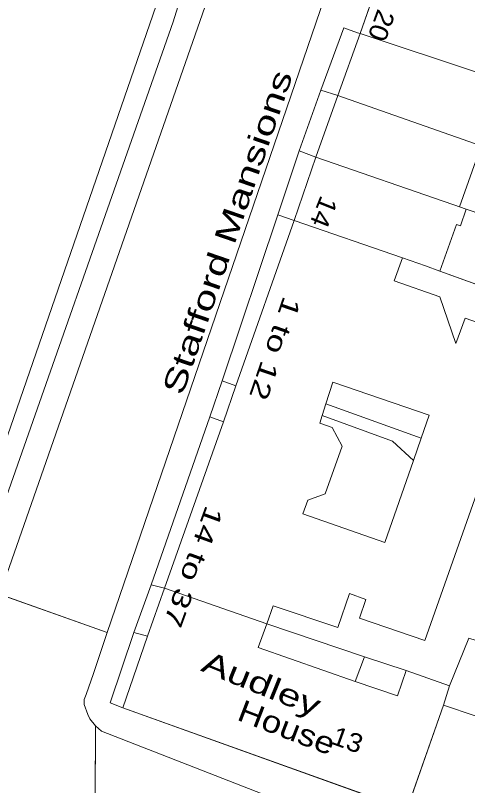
# Model space of a CAD drawing. Extents: x 528790 to 529292, y 179350 to 179856.
# Drawn here: x 529073.1 to 529109.4, y 179400.8 to 179462.8 of the extents above; entities that cross this region are included whole.
import ezdxf

# ---------------------------------------------------------------- set-up
doc = ezdxf.new("R2010")
doc.units = 0
doc.header["$LTSCALE"] = 0.6
doc.layers.add('1', color=7, linetype='Continuous', lineweight=13)
doc.layers.add('2', color=7, linetype='Continuous', lineweight=13)
doc.layers.add('5', color=7, linetype='Continuous')

msp = doc.modelspace()

# ---------------------------------------------------------------- linework, layer by layer
at = {"layer": '1'}
for points in [[(529114.4, 179506.25), (529113.95, 179506.4), (529113.55, 179506.6), (529113.05, 179506.9), (529109.35, 179500.6), (529109, 179500), (529106.6, 179495.95), (529103.106, 179489.891), (529101.15, 179486.5), (529097.9, 179480.65), (529096.6, 179478.45), (529092.35, 179471.1), (529087.2, 179468), (529087.15, 179466.8), (529086.55, 179464.8), (529085.75, 179462.3), (529070.05, 179417.6)], [(529068.6, 179417.95), (529086.15, 179468.75), (529075.3, 179473.5), (529070.95, 179475.45)], [(529104.55, 179398.9), (529081.7, 179407.1), (529080.7, 179407.5), (529082.6, 179413.15), (529084, 179417), (529088.7, 179430.5), (529089.7, 179433.4), (529094.18, 179446.76), (529095.9, 179451.9), (529097.65, 179456.8), (529099.5, 179461.8), (529100.6, 179461.4), (529100.8, 179461.35), (529102.6, 179466.5)], [(529098.25, 179465.2), (529080.46, 179413.16), (529079.34, 179409.86), (529078.75, 179408.15), (529078.6, 179407.75), (529078.6, 179407.35), (529078.9, 179406.55), (529079.05, 179406.2), (529079.5, 179405.65), (529080, 179405.2), (529096.7, 179398.7)], [(529072.2, 179417.3), (529088.7, 179464.65)], [(529118.65, 179438.1), (529107.225, 179442.232), (529106.05, 179442.65), (529104.2, 179443.3), (529103.55, 179441.45), (529107.2, 179440.15), (529108.5, 179436.4), (529109.25, 179438.45), (529114.5, 179436.6), (529106, 179412.5), (529100.75, 179414.3), (529101.25, 179415.8), (529099.95, 179416.3), (529099, 179413.55), (529093.8, 179415.3), (529093.3, 179413.85), (529101.15, 179411.2), (529104.5, 179410.1), (529108, 179408.85), (529109.55, 179412.7)], [(529079.47, 179394.39), (529079.5, 179405.65), (529079.05, 179406.2), (529078.9, 179406.55), (529078.6, 179407.35), (529078.6, 179407.75), (529078.75, 179408.15), (529079.34, 179409.86), (529080.46, 179413.16), (529071.39, 179416.36)], [(529096.7, 179398.7), (529080, 179405.2), (529079.5, 179405.65), (529079.47, 179394.39)]]:
    msp.add_lwpolyline(points, dxfattribs=at)
for points in [[(529098.25, 179465.2), (529099.6, 179467.2), (529101.25, 179469.3), (529102.95, 179471.55), (529104.35, 179473.5), (529107.6, 179479.8), (529101.31, 179483.07), (529100.25, 179481.25), (529098.95, 179478.8), (529097.6, 179476.3), (529096.35, 179473.9), (529094.8, 179471.55), (529094, 179470.3), (529093, 179469.05), (529089.8, 179465.7), (529088.7, 179464.65), (529072.2, 179417.3), (529072, 179416.9), (529071.7, 179416.55), (529071.39, 179416.36), (529080.46, 179413.16)], [(529085.75, 179462.3), (529086.55, 179464.8), (529087.15, 179466.8), (529087.2, 179468), (529086.5, 179469.6), (529076.4, 179475.4), (529075.3, 179473.5), (529086.15, 179468.75), (529068.6, 179417.95), (529070.05, 179417.6)], [(529114.2, 179462.65), (529110.6, 179464.05), (529110.25, 179464.2), (529102.6, 179466.5), (529100.8, 179461.35), (529110.4, 179458.15), (529111.6, 179461.5), (529113.55, 179460.8)], [(529100.8, 179461.35), (529100.6, 179461.4), (529099.5, 179461.8), (529097.65, 179456.8), (529099, 179456.35)], [(529110.55, 179452.3), (529117.6, 179449.9), (529118.95, 179450.5), (529119.8, 179453.05), (529119.15, 179454.65), (529110.4, 179458.15), (529100.8, 179461.35), (529099, 179456.35)], [(529097.25, 179451.4), (529099, 179456.35), (529097.65, 179456.8), (529095.9, 179451.9)], [(529108.802, 179447.406), (529110.55, 179452.3), (529099, 179456.35), (529097.25, 179451.4), (529108.25, 179447.599), (529108.426, 179447.536)], [(529095.9, 179451.9), (529094.18, 179446.76), (529095.5, 179446.3), (529097.25, 179451.4)], [(529121.65, 179446.25), (529122.4, 179448.3), (529117.6, 179449.9), (529110.55, 179452.3), (529108.802, 179447.406), (529109.342, 179447.216), (529120.62, 179443.39)], [(529109.342, 179447.216), (529108.802, 179447.406), (529108.426, 179447.536), (529108.25, 179447.599), (529097.25, 179451.4), (529095.5, 179446.3), (529104.2, 179443.3), (529106.05, 179442.65), (529107.225, 179442.232), (529108.544, 179445.988), (529108.87, 179445.874)], [(529090.8, 179433), (529095.5, 179446.3), (529094.18, 179446.76), (529089.7, 179433.4)], [(529109.342, 179447.216), (529108.87, 179445.874), (529108.544, 179445.988), (529107.225, 179442.232), (529118.65, 179438.1), (529120.62, 179443.39)], [(529095.5, 179446.3), (529090.8, 179433), (529089.8, 179430.1), (529085.05, 179416.71), (529093.3, 179413.85), (529093.8, 179415.3), (529099, 179413.55), (529099.95, 179416.3), (529101.25, 179415.8), (529100.75, 179414.3), (529106, 179412.5), (529114.5, 179436.6), (529109.25, 179438.45), (529108.5, 179436.4), (529107.2, 179440.15), (529103.55, 179441.45), (529104.2, 179443.3)], [(529089.8, 179430.1), (529090.8, 179433), (529089.7, 179433.4), (529088.7, 179430.5)], [(529105.1, 179427), (529102.8, 179420.4), (529096.2, 179422.7), (529096.6, 179423.8), (529098, 179424.3), (529099.35, 179428.15), (529098.55, 179429.65), (529097.55, 179430), (529097.75, 179430.6), (529098.05, 179431.55), (529098.6, 179433.3), (529106.35, 179430.65), (529105.7, 179428.8)], [(529105.7, 179428.8), (529106.35, 179430.65), (529098.6, 179433.3), (529098.05, 179431.55)], [(529098.05, 179431.55), (529097.75, 179430.6), (529103.4, 179428.55), (529105.1, 179427), (529105.7, 179428.8)], [(529088.7, 179430.5), (529084, 179417), (529085.05, 179416.71), (529089.8, 179430.1)], [(529097.75, 179430.6), (529097.55, 179430), (529098.55, 179429.65), (529099.35, 179428.15), (529098, 179424.3), (529096.6, 179423.8), (529096.2, 179422.7), (529102.8, 179420.4), (529105.1, 179427), (529103.4, 179428.55)], [(529083.7, 179412.85), (529081.7, 179407.1), (529104.55, 179398.9), (529107.5, 179407.3), (529108, 179408.85), (529104.5, 179410.1), (529103.8, 179408.05), (529100.4, 179409.2), (529092.6, 179411.95), (529093.3, 179413.85), (529085.05, 179416.71)], [(529085.05, 179416.71), (529084, 179417), (529082.6, 179413.15), (529083.7, 179412.85)], [(529101.15, 179411.2), (529093.3, 179413.85), (529092.6, 179411.95), (529100.4, 179409.2)], [(529083.7, 179412.85), (529082.6, 179413.15), (529080.7, 179407.5), (529081.7, 179407.1)], [(529108, 179408.85), (529107.5, 179407.3), (529112.6, 179405.6), (529111.75, 179403), (529114.9, 179401.9), (529116.25, 179405.6), (529111.9, 179407.2), (529113.4, 179411.45), (529109.55, 179412.7)], [(529100.4, 179409.2), (529103.8, 179408.05), (529104.5, 179410.1), (529101.15, 179411.2)], [(529114.9, 179401.9), (529111.75, 179403), (529112.6, 179405.6), (529107.5, 179407.3), (529104.55, 179398.9), (529110.606, 179396.76), (529112.105, 179396.231), (529112.9, 179395.95)]]:
    msp.add_lwpolyline(points, close=True, dxfattribs=at)
at = {"layer": '2'}
for p, q in [((529100.8, 179461.35), (529102.6, 179466.5)), ((529099, 179456.35), (529100.8, 179461.35)), ((529100.8, 179461.35), (529110.4, 179458.15)), ((529097.65, 179456.8), (529095.9, 179451.9)), ((529097.65, 179456.8), (529099, 179456.35)), ((529097.25, 179451.4), (529099, 179456.35)), ((529099, 179456.35), (529110.55, 179452.3)), ((529095.9, 179451.9), (529094.18, 179446.76)), ((529097.25, 179451.4), (529095.9, 179451.9)), ((529110.55, 179452.3), (529108.802, 179447.406)), ((529095.5, 179446.3), (529097.25, 179451.4)), ((529108.802, 179447.406), (529109.342, 179447.216)), ((529094.18, 179446.76), (529089.7, 179433.4)), ((529095.5, 179446.3), (529094.18, 179446.76)), ((529120.62, 179443.39), (529109.342, 179447.216)), ((529090.8, 179433), (529095.5, 179446.3)), ((529095.5, 179446.3), (529104.2, 179443.3)), ((529107.225, 179442.232), (529118.65, 179438.1)), ((529089.7, 179433.4), (529088.7, 179430.5)), ((529089.7, 179433.4), (529090.8, 179433)), ((529089.8, 179430.1), (529090.8, 179433)), ((529098.05, 179431.55), (529097.75, 179430.6)), ((529105.7, 179428.8), (529098.05, 179431.55)), ((529088.7, 179430.5), (529084, 179417)), ((529085.05, 179416.71), (529089.8, 179430.1)), ((529088.7, 179430.5), (529089.8, 179430.1)), ((529105.1, 179427), (529105.7, 179428.8)), ((529084, 179417), (529082.6, 179413.15)), ((529083.7, 179412.85), (529085.05, 179416.71)), ((529085.05, 179416.71), (529084, 179417)), ((529093.3, 179413.85), (529085.05, 179416.71)), ((529071.39, 179416.36), (529080.46, 179413.16)), ((529101.15, 179411.2), (529093.3, 179413.85)), ((529081.7, 179407.1), (529083.7, 179412.85)), ((529082.6, 179413.15), (529083.7, 179412.85)), ((529109.55, 179412.7), (529108, 179408.85)), ((529101.15, 179411.2), (529100.4, 179409.2)), ((529104.5, 179410.1), (529101.15, 179411.2)), ((529104.5, 179410.1), (529108, 179408.85)), ((529108, 179408.85), (529107.5, 179407.3)), ((529081.7, 179407.1), (529104.55, 179398.9)), ((529107.5, 179407.3), (529104.55, 179398.9)), ((529079.5, 179405.65), (529079.47, 179394.39))]:
    msp.add_line(p, q, dxfattribs=at)
for points in [[(529071.39, 179416.36), (529071.7, 179416.55), (529072, 179416.9), (529072.2, 179417.3), (529088.7, 179464.65), (529089.8, 179465.7), (529093, 179469.05), (529094, 179470.3), (529094.8, 179471.55), (529096.35, 179473.9), (529097.6, 179476.3), (529098.95, 179478.8), (529100.25, 179481.25), (529101.31, 179483.07)], [(529080.46, 179413.16), (529098.25, 179465.2), (529099.6, 179467.2), (529101.25, 179469.3), (529102.95, 179471.55), (529104.35, 179473.5), (529107.6, 179479.8)], [(529068.6, 179417.95), (529086.15, 179468.75), (529075.3, 179473.5)], [(529087.2, 179468), (529087.15, 179466.8), (529086.55, 179464.8), (529085.75, 179462.3), (529070.05, 179417.6), (529068.6, 179417.95)], [(529097.65, 179456.8), (529099.5, 179461.8), (529100.6, 179461.4), (529100.8, 179461.35)], [(529108.802, 179447.406), (529108.426, 179447.536), (529108.25, 179447.599), (529097.25, 179451.4)], [(529109.342, 179447.216), (529108.87, 179445.874), (529108.544, 179445.988), (529107.225, 179442.232)], [(529104.2, 179443.3), (529103.55, 179441.45), (529107.2, 179440.15), (529108.5, 179436.4), (529109.25, 179438.45), (529114.5, 179436.6), (529106, 179412.5), (529100.75, 179414.3), (529101.25, 179415.8), (529099.95, 179416.3), (529099, 179413.55), (529093.8, 179415.3), (529093.3, 179413.85)], [(529107.225, 179442.232), (529106.05, 179442.65), (529104.2, 179443.3)], [(529105.7, 179428.8), (529106.35, 179430.65), (529098.6, 179433.3), (529098.05, 179431.55)], [(529097.75, 179430.6), (529097.55, 179430), (529098.55, 179429.65), (529099.35, 179428.15), (529098, 179424.3), (529096.6, 179423.8), (529096.2, 179422.7), (529102.8, 179420.4), (529105.1, 179427)], [(529097.75, 179430.6), (529103.4, 179428.55), (529105.1, 179427)], [(529093.3, 179413.85), (529092.6, 179411.95), (529100.4, 179409.2)], [(529079.5, 179405.65), (529079.05, 179406.2), (529078.9, 179406.55), (529078.6, 179407.35), (529078.6, 179407.75), (529078.75, 179408.15), (529079.34, 179409.86), (529080.46, 179413.16)], [(529082.6, 179413.15), (529080.7, 179407.5), (529081.7, 179407.1)], [(529100.4, 179409.2), (529103.8, 179408.05), (529104.5, 179410.1)], [(529107.5, 179407.3), (529112.6, 179405.6), (529111.75, 179403), (529114.9, 179401.9)], [(529121.95, 179389.75), (529118.2, 179390.8), (529111.481, 179393.269), (529108.8, 179394.254), (529096.7, 179398.7), (529080, 179405.2), (529079.5, 179405.65)]]:
    msp.add_lwpolyline(points, dxfattribs=at)

# ---------------------------------------------------------------- texts
at = {"layer": '5'}
for s, height, rotation, width, p in [('20', 1.5, 250, 1.1, (529102.23, 179463.4)), ('Stafford Mansions', 1.75, 71, 1.45, (529086.5, 179432.15)), ('14', 1.5, 248, 1.1, (529097.65, 179448.4)), ('1 to 12', 1.5, 251, 1.4, (529094.65, 179440.3)), ('14 to 37', 1.5, 250, 1.4, (529088.41, 179423.46)), ('Audley', 1.75, 338, 1.4, (529087.9, 179410.1)), ('House', 1.75, 339, 1.2, (529090.8, 179406.15)), ('13', 1.5, 340, 1.1, (529098.38, 179404.23))]:
    msp.add_text(s, height=height, rotation=rotation, dxfattribs=dict(at, width=width)).set_placement(p)

doc.saveas('drawing.dxf')
